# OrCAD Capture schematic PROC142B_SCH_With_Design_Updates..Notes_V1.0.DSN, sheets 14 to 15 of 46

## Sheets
14 12. PERIPHERAL POWER SUPPLY-2: size C; title: PERIPHERAL POWER SUPPLIES-2
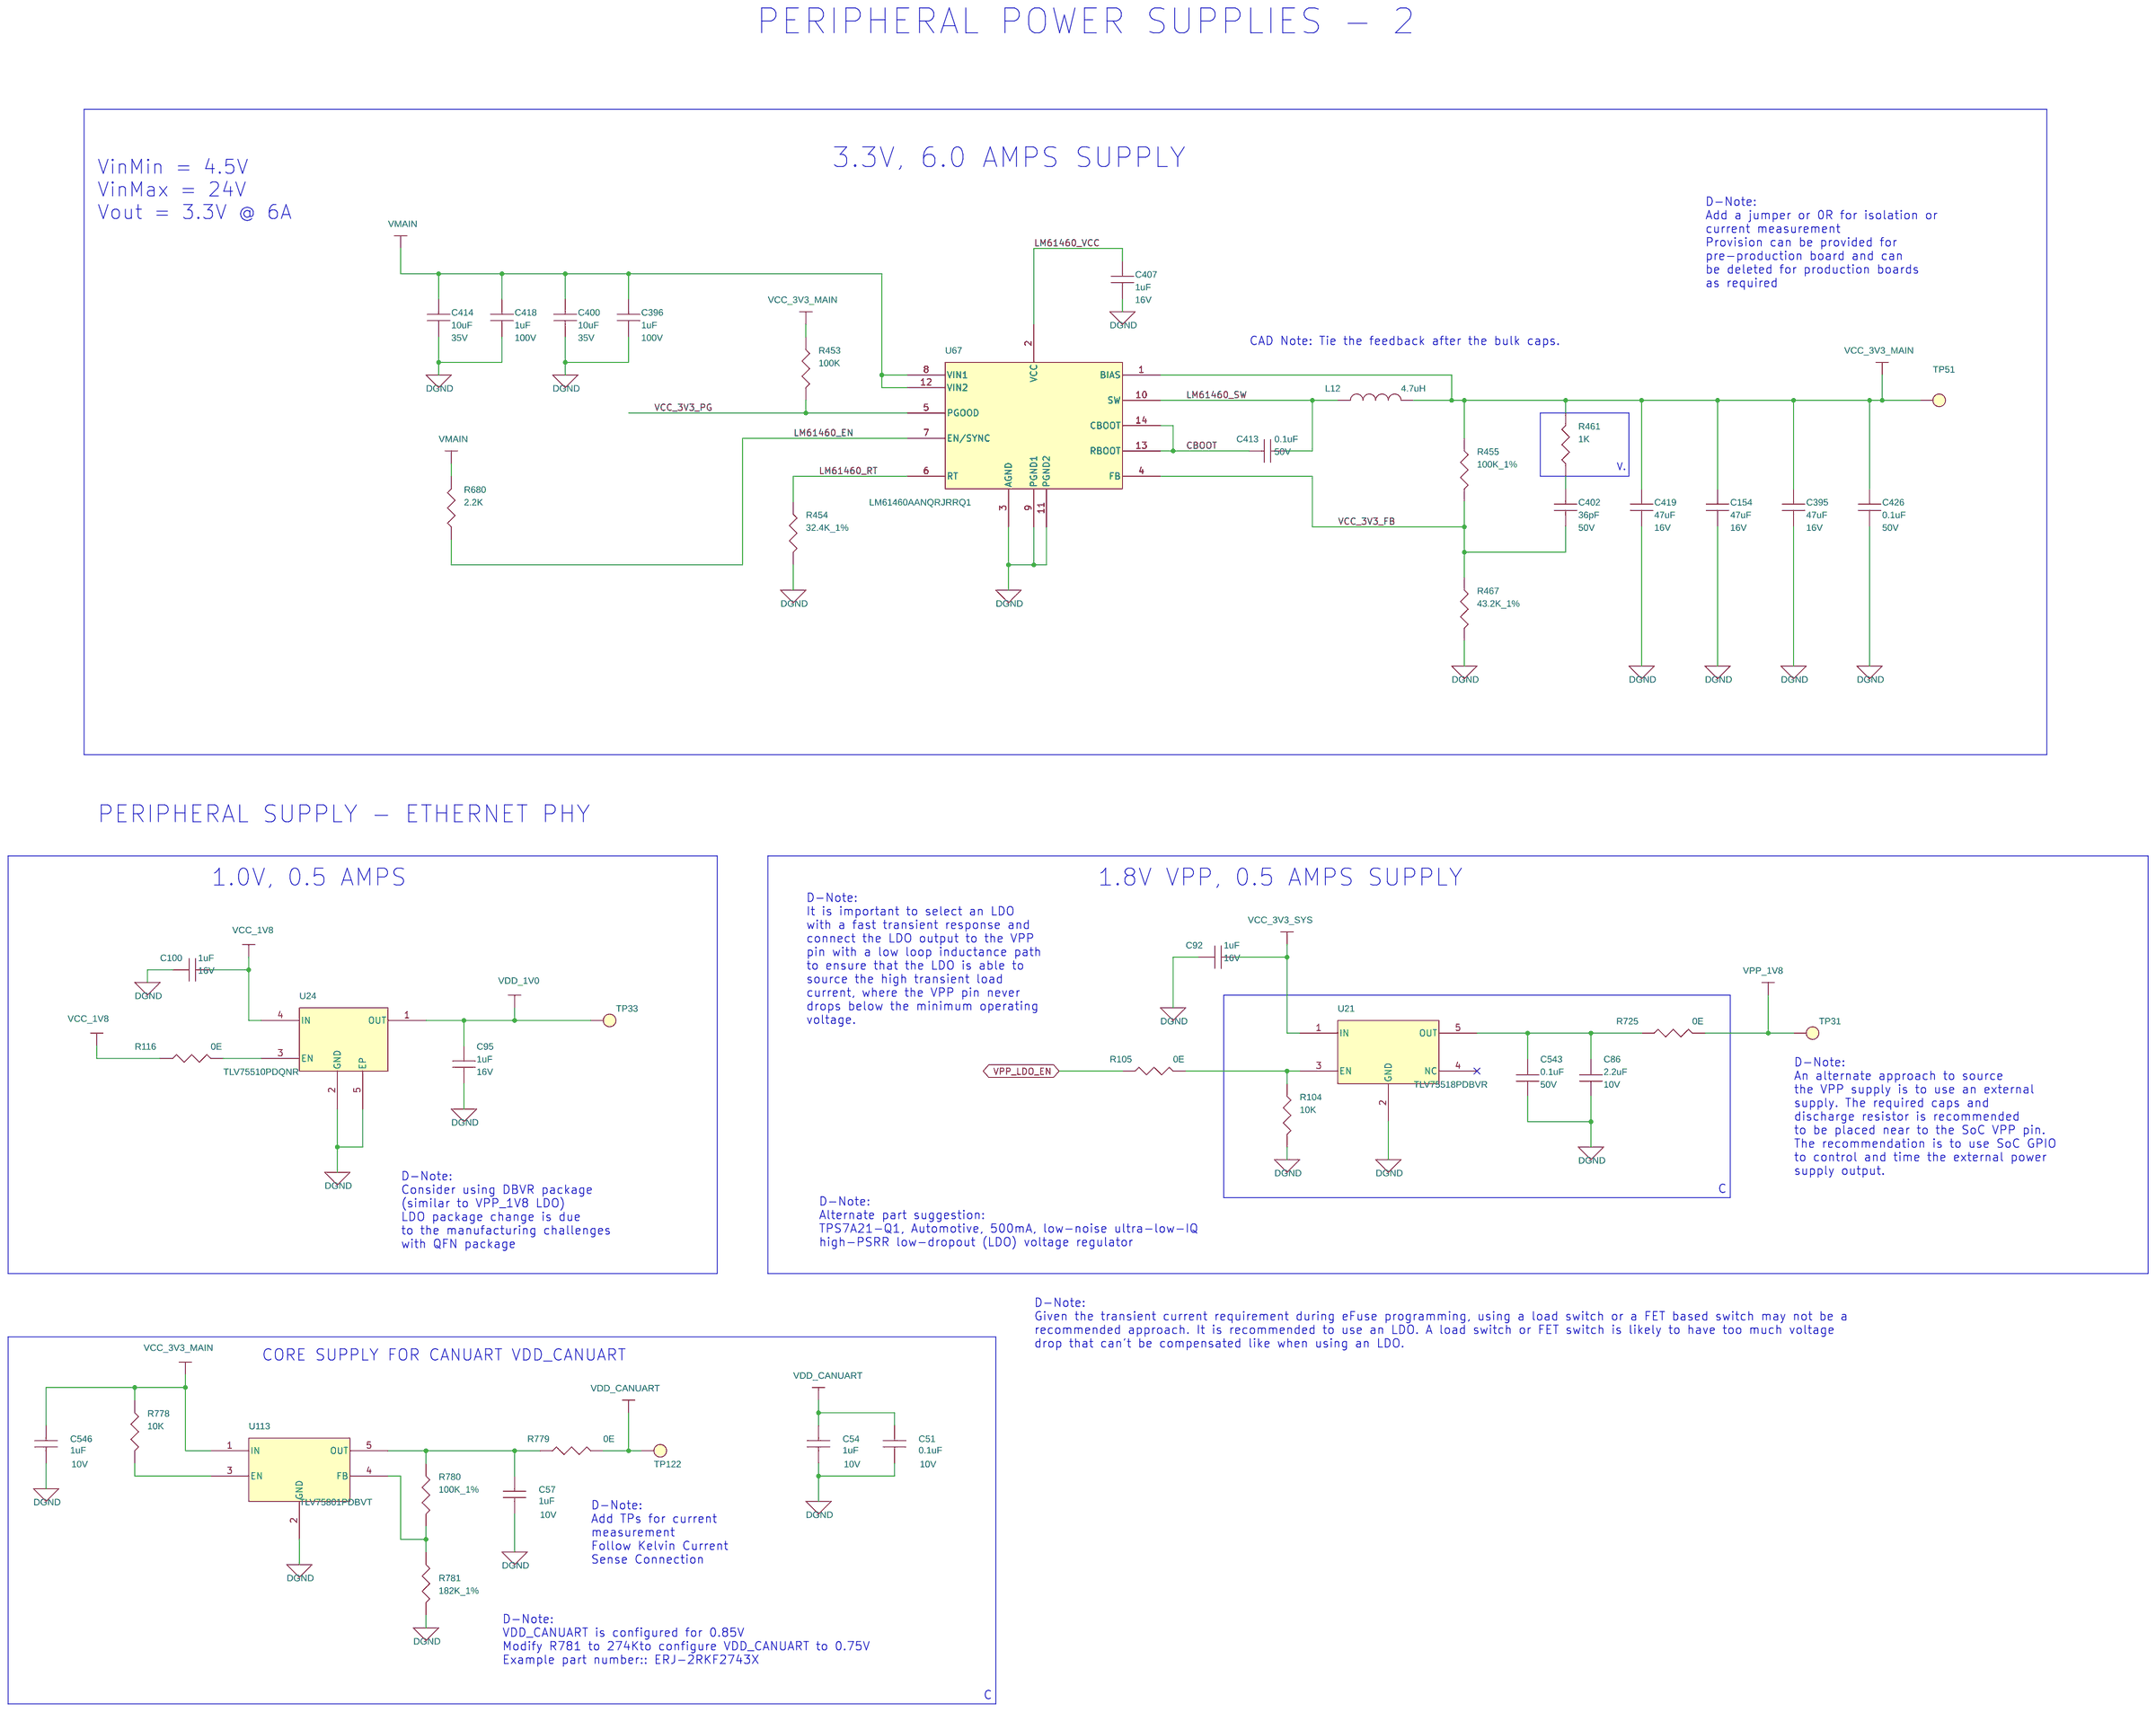
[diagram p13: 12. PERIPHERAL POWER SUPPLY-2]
15 13. FULTON PMIC: size C; title: SOC POWER SUPPLIES-PMIC BASED WITH SOC CURRENT MEASUREMENT SHUNTS
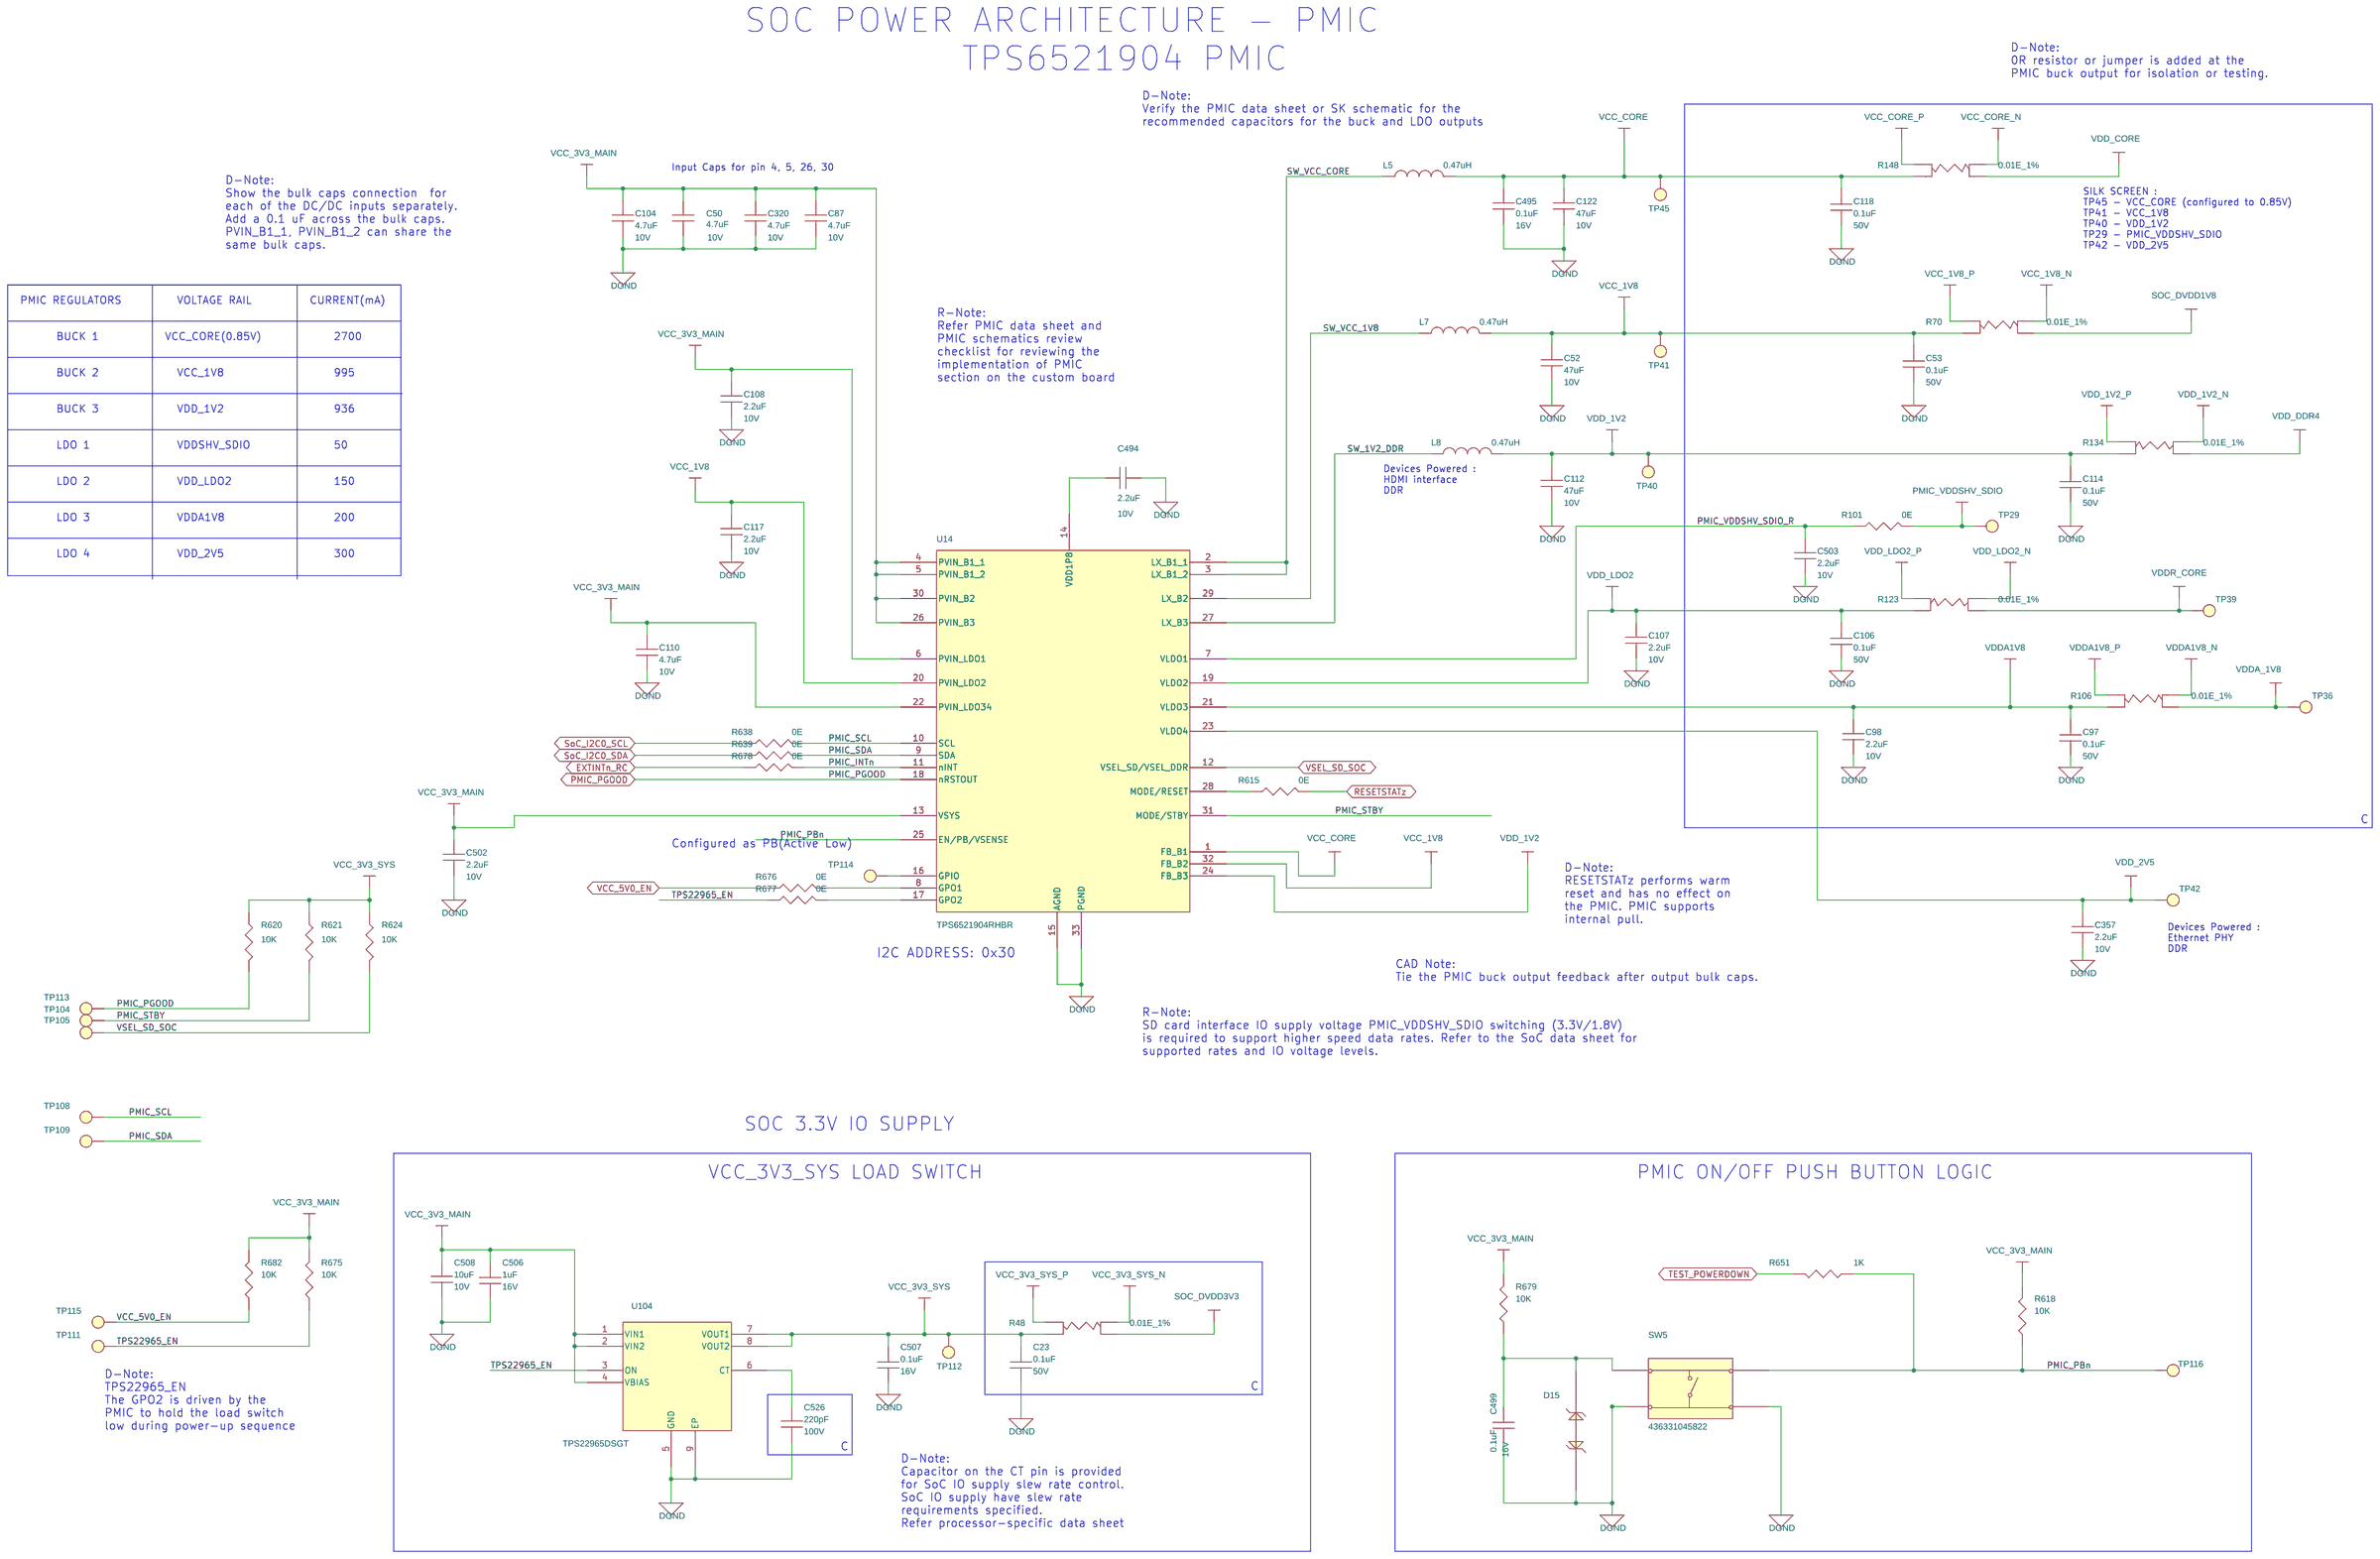
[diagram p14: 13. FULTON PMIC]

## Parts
sheet 12. PERIPHERAL POWER SUPPLY-2
C51  0.1uF  [CAP0201_0-5]
C54  1uF  [CAP0201_0-5]
C57  1uF  [CAP0201_0-5]
C86  2.2uF  [CAP0201_0-5]
C92  1uF  [CAP0201_0-5]
C95  1uF  [CAP0201_0-5]
C100  1uF  [CAP0201_0-5]
C154  47uF  [CAP1210_2-75]
C395  47uF  [CAP1210_2-75]
C396  1uF  [CAP0805_1-5]
C400  10uF  [CAP0603_1]
C402  36pF  [CAP0402_0-75]
C407  1uF  [CAP0201_0-5]
C413  0.1uF  [CAP0402_0-75]
C414  10uF  [CAP0603_1]
C418  1uF  [CAP0805_1-5]
C419  47uF  [CAP1210_2-75]
C426  0.1uF  [CAP0402_0-75]
C543  0.1uF  [CAP0402_0-75]
C546  1uF  [CAP0201_0-5]
L12  4.7uH  [IND_XAL6060_260X270_SMD_6-1]
R104  10K  [RES0201_0-5]
R105  0E  [RES0201_0-5]
R116  0E  [RES0201_0-5]
R453  100K  [RES0402_0-5]
R454  32.4K_1%  [RES0402_0-5]
R455  100K_1%  [RES0402_0-5]
R461  1K  [RES0402_0-5]
R467  43.2K_1%  [RES0402_0-5]
R680  2.2K  [RES0402_0-5]
R725  0E  [RES0805_0-75]
R778  10K  [RES0201_0-5]
R779  0E  [RES0402_0-5]
R780  100K_1%  [RES0402_0-5]
R781  182K_1%  [RES0402_0-5]
TP31  TP20_SMD  [TP20_SMD]
TP33  TP20_SMD  [TP20_SMD]
TP51  TP20_SMD  [TP20_SMD]
TP122  TP20_SMD  [TP20_SMD]
U21  TLV75518PDBVR  [SOT23-5_1-5]
U24  TLV75510PDQNR  [X2SON4_TLV71318P_40X40_0-4]
U67  LM61460AANQRJRRQ1  [VQFNHR14_LM61460_160X140_1]
U113  TLV75801PDBVT  [SOT23-5_1-5]
sheet 13. FULTON PMIC
C23  0.1uF  [CAP0402_0-75]
C50  4.7uF  [CAP0402_0-75]
C52  47uF  [CAP0805_1-5]
C53  0.1uF  [CAP0402_0-75]
C87  4.7uF  [CAP0402_0-75]
C97  0.1uF  [CAP0402_0-75]
C98  2.2uF  [CAP0201_0-5]
C104  4.7uF  [CAP0402_0-75]
C106  0.1uF  [CAP0402_0-75]
C107  2.2uF  [CAP0201_0-5]
C108  2.2uF  [CAP0201_0-5]
C110  4.7uF  [CAP0402_0-75]
C112  47uF  [CAP0805_1-5]
C114  0.1uF  [CAP0402_0-75]
C117  2.2uF  [CAP0201_0-5]
C118  0.1uF  [CAP0402_0-75]
C122  47uF  [CAP0805_1-5]
C320  4.7uF  [CAP0402_0-75]
C357  2.2uF  [CAP0201_0-5]
C494  2.2uF  [CAP0201_0-5]
C495  0.1uF  [CAP0201_0-5]
C499  0.1uF  [CAP0201_0-5]
C502  2.2uF  [CAP0201_0-5]
C503  2.2uF  [CAP0201_0-5]
C506  1uF  [CAP0201_0-5]
C507  0.1uF  [CAP0201_0-5]
C508  10uF  [CAP0402_0-75]
C526  220pF  [CAP0402_0-75]
D15  TPD1E10B06DPYR  [DIO_DFN0402_0-5]
L5  0.47uH  [IND0806_1-2]
L7  0.47uH  [IND0806_1-2]
L8  0.47uH  [IND0806_1-2]
R48  0.01E_1%  [RES_KRL3216T4_1206-4_0-7]
R70  0.01E_1%  [RES_KRL3216T4_1206-4_0-7]
R101  0E  [RES0402_0-5]
R106  0.01E_1%  [RES_KRL3216T4_1206-4_0-7]
R123  0.01E_1%  [RES_KRL3216T4_1206-4_0-7]
R134  0.01E_1%  [RES_KRL3216T4_1206-4_0-7]
R148  0.01E_1%  [RES_KRL3216T4_1206-4_0-7]
R615  0E  [RES0402_0-5]
R618  10K  [RES0201_0-5]
R620  10K  [RES0201_0-5]
R621  10K  [RES0201_0-5]
R624  10K  [RES0201_0-5]
R638  0E  [RES0201_0-5]
R639  0E  [RES0201_0-5]
R651  1K  [RES0402_0-5]
R675  10K  [RES0201_0-5]
R676  0E  [RES0201_0-5]
R677  0E  [RES0201_0-5]
R678  0E  [RES0201_0-5]
R679  10K  [RES0201_0-5]
R682  10K  [RES0201_0-5]
SW5  436331045822  [SW4_436331045822_190X190_SMD_1-7]
TP29  TP20_SMD  [TP20_SMD]
TP36  TP20_SMD  [TP20_SMD]
TP39  TP20_SMD  [TP20_SMD]
TP40  TP20_SMD  [TP20_SMD]
TP41  TP20_SMD  [TP20_SMD]
TP42  TP20_SMD  [TP20_SMD]
TP45  TP20_SMD  [TP20_SMD]
TP104  TP20_SMD  [TP20_SMD]
TP105  TP20_SMD  [TP20_SMD]
TP108  TP20_SMD  [TP20_SMD]
TP109  TP20_SMD  [TP20_SMD]
TP111  TP20_SMD  [TP20_SMD]
TP112  TP20_SMD  [TP20_SMD]
TP113  TP20_SMD  [TP20_SMD]
TP114  TP20_SMD  [TP20_SMD]
TP115  TP20_SMD  [TP20_SMD]
TP116  TP20_SMD  [TP20_SMD]
U14  TPS6521904RHBR  [QFN32_19-68_200X200_1_EP3-8]
U104  TPS22965DSGT  [WSON8_19-68_80X80_0-8]

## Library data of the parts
C51 = CAP: CAP CERAMIC 0.1uF 10V 10% X5R 0201; Chkd/date: MANIRAJA/290421; Crtd /date: ALVY/290421; Custom_Duty: 15%; Customs_HS_Code: 85322990; Distributor_name: DIGIKEY; Distributor_part_number: 1276-1115-1-ND; Footprint Path: Y:\MIS_DATABASE\Library\ALTIUM_TOOL\PCB_FOOTPRINTS\Altium_Footprint_Lib.PcbLib; Height: 0.33MM; Library Path: Y:\MIS_DATABASE\Library\ALTIUM_TOOL\SCHEMATICS_PARTS\MS_DISCRETE_Library.schlib; Mfr_name: SAMSUNG; Mfr_part_number: CL03A104KP3NNNC; Mistral Part No: 120009050017-R; Package: 0201; Part_type: CAPACITORS\CERAMIC; Project: SRMS-SAR_BRD; RoHS: RoHS; Temperature: -55°C+85°C; Tolerance: 10%; Voltage: 10V; Wattage: NA; Weight: 0.33mg; Datasheet: Y:\MIS_DATABASE\DATASHEETS\CAPACITORS\CL03A104KP3NNNC.PDF
C54 C57 C546 = CAP: CAP CERAMIC 1uF 10V 20% X5R 0201; Chkd/date: NAVEED/070415; Crtd /date: VASANTHA/230314; Custom_Duty: 15%; Customs_HS_Code: 85322990; Distributor_name: DIGIKEY; Distributor_part_number: 1276-1324-1-ND; Footprint Path: Y:\MIS_DATABASE\Library\ALTIUM_TOOL\PCB_FOOTPRINTS\Altium_Footprint_Lib.PcbLib; Height: 0.35MM; Library Path: Y:\MIS_DATABASE\Library\ALTIUM_TOOL\SCHEMATICS_PARTS\MS_DISCRETE_Library.schlib; Mfr_name: SAMSUNG; Mfr_part_number: CL03A105MP3NSNC; Mistral Part No: 120015030003-R; Package: 0201; Part_type: CAPACITORS\CERAMIC; Project: DUET BOARDS; RoHS: RoHS; Temperature: -55°C+85°C; Tolerance: 20%; Voltage: 10V; Wattage: NA; Weight: 0.17mg; Datasheet: Y:\MIS_DATABASE\DATASHEETS\CAPACITORS\CL03A105MP3NSNC.PDF
C86 C494 C502 = CAP: CAP CERAMIC 2.2uF 10V 10% X5R 0201; Chkd/date: MANIRAJA/220918; Crtd /date: MANIRAJA/220918; Custom_Duty: 15%; Customs_HS_Code: 85322990; Distributor_name: DIGIKEY; Distributor_part_number: 490-13227-1-ND; Footprint Path: Y:\MIS_DATABASE\Library\ALTIUM_TOOL\PCB_FOOTPRINTS\Altium_Footprint_Lib.PcbLib; Height: 0.39MM; Library Path: Y:\MIS_DATABASE\Library\ALTIUM_TOOL\SCHEMATICS_PARTS\MS_DISCRETE_Library.schlib; Mfr_name: MURATA; Mfr_part_number: GRM033R61A225KE47D; Mistral Part No: 120018090044-R; Package: 0201; Part_type: CAPACITORS\CERAMIC; Project: TI_60GHz-AOP; RoHS: RoHS; Temperature: -55°C+85°C; Tolerance: 10%; Voltage: 10V; Wattage: NA; Weight: 0.33mg; Datasheet: Y:\MIS_DATABASE\DATASHEETS\CAPACITORS\GRM033R61A225KE47D.PDF
C92 C95 C100 C407 C506 = CAP: CAP CERAMIC 1uF 16V 20% X5R 0201; Chkd/date: MANIRAJA/300520; Crtd /date: ALVY/260520; Custom_Duty: 15%; Customs_HS_Code: 85322990; Distributor_name: DIGIKEY; Distributor_part_number: 490-18654-1-ND; Footprint Path: Y:\MIS_DATABASE\Library\ALTIUM_TOOL\PCB_FOOTPRINTS\Altium_Footprint_Lib.PcbLib; Height: 0.39MM; Library Path: Y:\MIS_DATABASE\Library\ALTIUM_TOOL\SCHEMATICS_PARTS\MS_DISCRETE_Library.schlib; Mfr_name: MURATA; Mfr_part_number: GRM033R61C105ME15D; Mistral Part No: 120018090038-R; Package: 0201; Part_type: CAPACITORS\CERAMIC; Project: QCS610_NANOSOM; RoHS: RoHS; Temperature: -55°C+85°C; Tolerance: 20%; Voltage: 16V; Wattage: NA; Weight: 0.33mg; Datasheet: Y:\MIS_DATABASE\DATASHEETS\CAPACITORS\GRM033R61C105ME15.PDF
C154 C395 C419 = CAP: CAP CERAMIC 47uF 16V 10% X6S 1210; Chkd/date: ALVY/010721; Crtd /date: MANIRAJA/010721; Custom_Duty: 15%; Customs_HS_Code: 85322990; Distributor_name: DIGIKEY; Distributor_part_number: 490-10531-1-ND; Footprint Path: Y:\MIS_DATABASE\Library\ALTIUM_TOOL\PCB_FOOTPRINTS\Altium_Footprint_Lib.PcbLib; Height: 2.70MM; Library Path: Y:\MIS_DATABASE\Library\ALTIUM_TOOL\SCHEMATICS_PARTS\MS_DISCRETE_Library.schlib; Mfr_name: MURATA; Mfr_part_number: GRM32EC81C476KE15L; Mistral Part No: 120021070001-R; Package: 1210; Part_type: CAPACITORS\CERAMIC; Project: TI_AM263X_CC; RoHS: RoHS; Temperature: -55°C+105°C; Tolerance: 10%; Voltage: 16V; Wattage: NA; Weight: 100mg; Datasheet: Y:\MIS_DATABASE\DATASHEETS\CAPACITORS\GRM32EC81C476KE15.PDF
C396 C418 = CAP: CAP CERAMIC 1uF 100V 10% X7S 0805; Chkd/date: MANIRAJA/160921; Crtd /date: ALVY/150921; Custom_Duty: 15%; Customs_HS_Code: 85322990; Distributor_name: DIGIKEY; Distributor_part_number: 490-14464-1-ND; Footprint Path: Y:\MIS_DATABASE\Library\ALTIUM_TOOL\PCB_FOOTPRINTS\Altium_Footprint_Lib.PcbLib; Height: 1.45MM; Library Path: Y:\MIS_DATABASE\Library\ALTIUM_TOOL\SCHEMATICS_PARTS\MS_DISCRETE_Library.schlib; Mfr_name: MURATA; Mfr_part_number: GRM21BC72A105KE01L; Mistral Part No: 120013030002-R; Package: 0805; Part_type: CAPACITORS\CERAMIC; Project: TI_AM62x SKEVM_BRD; RoHS: RoHS; Temperature: -55°C+125°C; Tolerance: 10%; Voltage: 100V; Wattage: NA; Weight: 6.4mg; Datasheet: Y:\MIS_DATABASE\DATASHEETS\CAPACITORS\GRM21BC72A105KE01.PDF
C400 C414 = CAP: CAP CERAMIC 10uF 35V 20% X5R 0603; Chkd/date: MANIRAJA/170519; Crtd /date: ALVY/160519; Custom_Duty: 15%; Customs_HS_Code: 85322990; Distributor_name: DIGIKEY; Distributor_part_number: 490-13248-1-ND; Footprint Path: Y:\MIS_DATABASE\Library\ALTIUM_TOOL\PCB_FOOTPRINTS\Altium_Footprint_Lib.PcbLib; Height: 1.00MM; Library Path: Y:\MIS_DATABASE\Library\ALTIUM_TOOL\SCHEMATICS_PARTS\MS_DISCRETE_Library.schlib; Mfr_name: MURATA; Mfr_part_number: GRM188R6YA106MA73D; Mistral Part No: 120019050016-R; Package: 0603; Part_type: CAPACITORS\CERAMIC; Project: BRUKER_SD820_COMMONDO; RoHS: RoHS; Temperature: -55°C+85°C; Tolerance: 20%; Voltage: 35V; Wattage: NA; Weight: 9mg; Datasheet: Y:\MIS_DATABASE\DATASHEETS\CAPACITORS\GRM188R6YA106MA73.PDF
C402 = CAP: CAP CERAMIC 36pF 50V 2% HI-Q C0G(NP0) 0402; Chkd/date: MANIRAJA/061021; Crtd /date: ALVY/051021; Custom_Duty: 15%; Customs_HS_Code: 85322990; Distributor_name: DIGIKEY; Distributor_part_number: 490-GJM1555C1H360GB01DTR-ND; Footprint Path: Y:\MIS_DATABASE\Library\ALTIUM_TOOL\PCB_FOOTPRINTS\Altium_Footprint_Lib.PcbLib; Height: 0.55MM; Library Path: Y:\MIS_DATABASE\Library\ALTIUM_TOOL\SCHEMATICS_PARTS\MS_DISCRETE_Library.schlib; Mfr_name: MURATA; Mfr_part_number: GJM1555C1H360GB01D; Mistral Part No: 120021100002-R; Package: 0402; Part_type: CAPACITORS\CERAMIC; Project: TI_AM62x SKEVM_BRD; RoHS: RoHS; Temperature: -55°C+125°C; Tolerance: 2%; Voltage: 50V; Wattage: NA; Weight: 1.5mg; Datasheet: Y:\MIS_DATABASE\DATASHEETS\CAPACITORS\GJM1555C1H360GB01.PDF
C413 C426 = CAP: CAP CERAMIC 0.1uF 50V 10% X7R 0402; Chkd/date: MANIRAJA/261020; Crtd /date: ALVY/211020; Custom_Duty: 15%; Customs_HS_Code: 85322990; Distributor_name: DIGIKEY; Distributor_part_number: 490-10700-1-ND; Footprint Path: Y:\MIS_DATABASE\Library\ALTIUM_TOOL\PCB_FOOTPRINTS\Altium_Footprint_Lib.PcbLib; Height: 0.55MM; Library Path: Y:\MIS_DATABASE\Library\ALTIUM_TOOL\SCHEMATICS_PARTS\MS_DISCRETE_Library.schlib; Mfr_name: MURATA; Mfr_part_number: GRM155R71H104KE14D; Mistral Part No: 120011100014-R; Package: 0402; Part_type: CAPACITORS\CERAMIC; Project: J7_CP; RoHS: RoHS; Temperature: -55°C+125°C; Tolerance: 10%; Voltage: 50V; Wattage: NA; Weight: 3.1mg; Datasheet: Y:\MIS_DATABASE\DATASHEETS\CAPACITORS\GRM155R71H104KE14.PDF
C23 C53 C97 C106 C114 C118 C543 = CAP: CAP CERAMIC 0.1uF 50V 10% X7R 0402; Alt_Mfr_name: YAGEO AMERICA; Alt_Mfr_part_number: CC0402KRX5R8BB104; Chkd/date: MANIRAJA/261020; Crtd /date: ALVY/211020; Custom_Duty: 15%; Customs_HS_Code: 85322990; Distributor_name: DIGIKEY; Distributor_part_number: 490-10700-1-ND; Footprint Path: Y:\MIS_DATABASE\Library\ALTIUM_TOOL\PCB_FOOTPRINTS\Altium_Footprint_Lib.PcbLib; Height: 0.55MM; Library Path: Y:\MIS_DATABASE\Library\ALTIUM_TOOL\SCHEMATICS_PARTS\MS_DISCRETE_Library.schlib; Mfr_name: MURATA; Mfr_part_number: GRM155R71H104KE14D; Mistral Part No: 120011100014-R; Package: 0402; Part_type: CAPACITORS\CERAMIC; Project: J7_CP; RoHS: RoHS; Temperature: -55°C+125°C; Tolerance: 10%; Voltage: 50V; Wattage: NA; Weight: 3.1mg; Datasheet: Y:\MIS_DATABASE\DATASHEETS\CAPACITORS\GRM155R71H104KE14.PDF
L12 = INDUCTOR: IND POWER 4.7uH 11A 20% SMD; Chkd/date: VASANTHA/090317; Crtd /date: MANIRAJA/090317; Custom_Duty: 15%; Customs_HS_Code: 85412900; Distributor_name: MOUSER; Distributor_part_number: 994-XAL6060-472MEB; Footprint Path: Y:\MIS_DATABASE\Library\ALTIUM_TOOL\PCB_FOOTPRINTS\Altium_Footprint_Lib.PcbLib; Height: 6.10MM; Library Path: Y:\MIS_DATABASE\Library\ALTIUM_TOOL\SCHEMATICS_PARTS\MS_DISCRETE_Library.schlib; Mfr_name: COILCRAFT; Mfr_part_number: XAL6060-472MEB; Mistral Part No: 130015090013-R; Package: SMD; Project: OCTBTS_3000; RoHS: RoHS; Temperature: -40°C+125°C; Tolerance: 20%; Voltage: NA; Wattage: NA; Weight: 1600g; Datasheet: Y:\MIS_DATABASE\DATASHEETS\DISCRETES\INDUCTORS\XAL6060-SER.PDF
R104 R778 = RESISTOR: RES 10K 1/20W 5% 0201; Chkd/date: MANIRAJA/050517; Crtd /date: MANIRAJA/050517; Custom_Duty: 15%; Customs_HS_Code: 85332119; Distributor_name: DIGIKEY; Distributor_part_number: 311-10KNCT-ND; Footprint Path: Y:\MIS_DATABASE\Library\ALTIUM_TOOL\PCB_FOOTPRINTS\Altium_Footprint_Lib.PcbLib; Height: 0.26MM; Library Path: Y:\MIS_DATABASE\Library\ALTIUM_TOOL\SCHEMATICS_PARTS\MS_DISCRETE_Library.schlib; Mfr_name: YAGEO AMERICA; Mfr_part_number: RC0201JR-0710KL; Mistral Part No: 110010070051-R; Package: 0201; Part_type: RESISTORS\FIXED; Project: GOLDEN-I LITE; RoHS: RoHS; Temperature: -55°C+125°C; Tolerance: 5%; Voltage: NA; Wattage: 1/20W; Weight: 0.17mg; Datasheet: Y:\MIS_DATABASE\DATASHEETS\RESISTORS\RCXXXXL-SER_MAR18.PDF
R105 R116 R638 R639 R676-R678 = RESISTOR: RES 0E 1/20W 5% 0201; Chkd/date: NAVEED/301214; Crtd /date: MUDDU/120710; Custom_Duty: 15%; Customs_HS_Code: 85332119; Distributor_name: DIGIKEY; Distributor_part_number: 311-0.0NCT-ND; Footprint Path: Y:\MIS_DATABASE\Library\ALTIUM_TOOL\PCB_FOOTPRINTS\Altium_Footprint_Lib.PcbLib; Height: 0.26MM; Library Path: Y:\MIS_DATABASE\Library\ALTIUM_TOOL\SCHEMATICS_PARTS\MS_DISCRETE_Library.schlib; Mfr_name: YAGEO AMERICA; Mfr_part_number: RC0201JR-070RL; Mistral Part No: 110010070067-R; Package: 0201; Part_type: RESISTORS\FIXED; Project: PB_BUGBASE; RoHS: RoHS; Temperature: -55°C+125°C; Tolerance: 5%; Voltage: NA; Wattage: 1/20W; Weight: 0.17mg; Datasheet: Y:\MIS_DATABASE\DATASHEETS\RESISTORS\RCXXXXL-SER_MAR18.PDF
R453 = RESISTOR: RES 100K 1/16W 5% 0402; Chkd/date: MANIRAJA/100717; Crtd /date: MANIRAJA/100717; Custom_Duty: 15%; Customs_HS_Code: 85332119; Distributor_name: DIGIKEY; Distributor_part_number: 311-100KJRCT-ND; Footprint Path: Y:\MIS_DATABASE\Library\ALTIUM_TOOL\PCB_FOOTPRINTS\Altium_Footprint_Lib.PcbLib; Height: 0.40MM; Library Path: Y:\MIS_DATABASE\Library\ALTIUM_TOOL\SCHEMATICS_PARTS\MS_DISCRETE_Library.schlib; Mfr_name: YAGEO AMERICA; Mfr_part_number: RC0402JR-07100KL; Mistral Part No: 110011060002-R; Package: 0402; Part_type: RESISTORS\FIXED; Project: DM8147_PCI CARD; RoHS: RoHS; Temperature: -55°C+155°C; Tolerance: 5%; Voltage: NA; Wattage: 1/16W; Weight: 0.65mg; Datasheet: Y:\MIS_DATABASE\DATASHEETS\RESISTORS\RCXXXXL-SER_MAR18.PDF
R454 = RESISTOR: RES 32.4K 1/16W 1% 0402; Chkd/date: MANIRAJA/080420; Crtd /date: ALVY/080420; Custom_Duty: 15%; Customs_HS_Code: 85332119; Distributor_name: DIGIKEY; Distributor_part_number: 541-32.4KLCT-ND; Footprint Path: Y:\MIS_DATABASE\Library\ALTIUM_TOOL\PCB_FOOTPRINTS\Altium_Footprint_Lib.PcbLib; Height: 0.40MM; Library Path: Y:\MIS_DATABASE\Library\ALTIUM_TOOL\SCHEMATICS_PARTS\MS_DISCRETE_Library.schlib; Mfr_name: VISHAY; Mfr_part_number: CRCW040232K4FKED; Mistral Part No: 110020040003-R; Package: 0402; Part_type: RESISTORS\FIXED; Project: HSDTRS_FEE_BRD; RoHS: RoHS; Temperature: -55°C+155°C; Tolerance: 1%; Voltage: NA; Wattage: 1/16W; Weight: 0.65mg; Datasheet: Y:\MIS_DATABASE\DATASHEETS\RESISTORS\CRCW0603.PDF
R455 R780 = RESISTOR: RES 100K 1/10W 1% 0402; Chkd/date: VASANTHA/201216; Crtd /date: MAZHAR/130306; Custom_Duty: 15%; Customs_HS_Code: 85332119; Distributor_name: DIGIKEY; Distributor_part_number: P100KLCT-ND; Footprint Path: Y:\MIS_DATABASE\Library\ALTIUM_TOOL\PCB_FOOTPRINTS\Altium_Footprint_Lib.PcbLib; Height: 0.40MM; Library Path: Y:\MIS_DATABASE\Library\ALTIUM_TOOL\SCHEMATICS_PARTS\MS_DISCRETE_Library.schlib; Mfr_name: PANASONIC-ECG; Mfr_part_number: ERJ-2RKF1003X; Mistral Part No: 110009030187-R; Package: 0402; Part_type: RESISTORS\FIXED; Project: J32; RoHS: RoHS; Temperature: -55°C+155°C; Tolerance: 1%; Voltage: NA; Wattage: 1/10W; Weight: 0.8mg; Datasheet: Y:\MIS_DATABASE\DATASHEETS\RESISTORS\PAN-ERJSER_NOV17.PDF
R461 R651 = RESISTOR: RES 1K 1/10W 5% 0402; Chkd/date: VASANTHA/201216; Crtd /date: MAZHAR/230805; Custom_Duty: 15%; Customs_HS_Code: 85332119; Distributor_name: DIGIKEY; Distributor_part_number: P1.0KJCT-ND; Footprint Path: Y:\MIS_DATABASE\Library\ALTIUM_TOOL\PCB_FOOTPRINTS\Altium_Footprint_Lib.PcbLib; Height: 0.40MM; Library Path: Y:\MIS_DATABASE\Library\ALTIUM_TOOL\SCHEMATICS_PARTS\MS_DISCRETE_Library.schlib; Mfr_name: PANASONIC-ECG; Mfr_part_number: ERJ-2GEJ102X; Mistral Part No: 110009030400-R; Package: 0402; Part_type: RESISTORS\FIXED; Project: HSE; RoHS: RoHS; Temperature: -55°C+155°C; Tolerance: 5%; Voltage: NA; Wattage: 1/10W; Weight: 0.8mg; Datasheet: Y:\MIS_DATABASE\DATASHEETS\RESISTORS\PAN-ERJSER_NOV17.PDF
R467 = RESISTOR: RES 43.2K 1/16W 1% 0402; Chkd/date: MANIRAJA/250821; Crtd /date: ALVY/250821; Custom_Duty: 15%; Customs_HS_Code: 85332119; Distributor_name: DIGIKEY; Distributor_part_number: 541-43.2KLCT-ND; Footprint Path: Y:\MIS_DATABASE\Library\ALTIUM_TOOL\PCB_FOOTPRINTS\Altium_Footprint_Lib.PcbLib; Height: 0.40MM; Library Path: Y:\MIS_DATABASE\Library\ALTIUM_TOOL\SCHEMATICS_PARTS\MS_DISCRETE_Library.schlib; Mfr_name: VISHAY; Mfr_part_number: CRCW040243K2FKED; Mistral Part No: 110021080019-R; Package: 0402; Part_type: RESISTORS\FIXED; Project: TI_AM62x SKEVM_BRD; RoHS: RoHS; Temperature: -55°C+155°C; Tolerance: 1%; Voltage: NA; Wattage: 1/16W; Weight: 0.65mg; Datasheet: Y:\MIS_DATABASE\DATASHEETS\RESISTORS\CRCW0603.PDF
R680 = RESISTOR: RES 2.2K 1/16W 5% 0402; Chkd/date: VASANTHA/061216; Crtd /date: BAVISH/021210; Custom_Duty: 15%; Customs_HS_Code: 85332119; Distributor_name: DIGIKEY; Distributor_part_number: 311-2.2KJRCT-ND; Footprint Path: Y:\MIS_DATABASE\Library\ALTIUM_TOOL\PCB_FOOTPRINTS\Altium_Footprint_Lib.PcbLib; Height: 0.40MM; Library Path: Y:\MIS_DATABASE\Library\ALTIUM_TOOL\SCHEMATICS_PARTS\MS_DISCRETE_Library.schlib; Mfr_name: YAGEO AMERICA; Mfr_part_number: RC0402JR-072K2L; Mistral Part No: 110010120018-R; Package: 0402; Part_type: RESISTORS\FIXED; Project: TE4; RoHS: RoHS; Temperature: -55°C+155°C; Tolerance: 5%; Voltage: NA; Wattage: 1/16W; Weight: 0.65mg; Datasheet: Y:\MIS_DATABASE\DATASHEETS\RESISTORS\RCXXXXL-SER_MAR18.PDF
R725 = RESISTOR: RES 0E 1/8W 5% 0805; Chkd/date: VASANTHA/130416; Crtd /date: JEBRAN/020316; Custom_Duty: 15%; Customs_HS_Code: 85332119; Distributor_name: DIGIKEY; Distributor_part_number: 311-0.0ARCT-ND; Footprint Path: Y:\MIS_DATABASE\Library\ALTIUM_TOOL\PCB_FOOTPRINTS\Altium_Footprint_Lib.PcbLib; Height: 0.60MM; Library Path: Y:\MIS_DATABASE\Library\ALTIUM_TOOL\SCHEMATICS_PARTS\MS_DISCRETE_Library.schlib; Mfr_name: YAGEO AMERICA; Mfr_part_number: RC0805JR-070RL; Mistral Part No: 110009030074-R; Package: 0805; Part_type: RESISTORS\FIXED; Project: ZK_BIOMETRIC; RoHS: RoHS; Temperature: -55°C+155°C; Tolerance: 5%; Voltage: NA; Wattage: 1/8W; Weight: 5.5mg; Datasheet: Y:\MIS_DATABASE\DATASHEETS\RESISTORS\RCXXXXL-SER_MAR18.PDF
R779 = RESISTOR: RES 0E 1/10W JUMPER 0402; Chkd/date: VASANTHA/061216; Crtd /date: NAVEED/201014; Custom_Duty: 15%; Customs_HS_Code: 85332119; Distributor_name: DIGIKEY; Distributor_part_number: P0.0JCT-ND; Footprint Path: Y:\MIS_DATABASE\Library\ALTIUM_TOOL\PCB_FOOTPRINTS\Altium_Footprint_Lib.PcbLib; Height: 0.40MM; IBISSP_MODLES: VALUE REPEATING 2 TIME; Library Path: Y:\MIS_DATABASE\Library\ALTIUM_TOOL\SCHEMATICS_PARTS\MS_DISCRETE_Library.schlib; Mfr_name: PANASONIC-ECG; Mfr_part_number: ERJ-2GE0R00X; Mistral Part No: 110018030052-R; Package: 0402; Part_type: RESISTORS\FIXED; Project: AEGIS POM; RoHS: RoHS; Temperature: -55°C+155°C; Tolerance: NA; Voltage: NA; Wattage: 1/10W; Weight: 0.8mg; Datasheet: Y:\MIS_DATABASE\DATASHEETS\RESISTORS\PAN-ERJSER_NOV17.PDF
R781 = RESISTOR: RES 182K 1/16W 1% 0402; Chkd/date: ALVY/210122; Crtd /date: TAMILARASU/210122; Custom_Duty: 15%; Customs_HS_Code: 85332119; Distributor_name: DIGIKEY; Distributor_part_number: YAG3015CT-ND; Footprint Path: Y:\MIS_DATABASE\Library\ALTIUM_TOOL\PCB_FOOTPRINTS\Altium_Footprint_Lib.PcbLib; Height: 0.40MM; Library Path: Y:\MIS_DATABASE\Library\ALTIUM_TOOL\SCHEMATICS_PARTS\MS_DISCRETE_Library.schlib; Mfr_name: YAGEO AMERICA; Mfr_part_number: RC0402FR-07182KL; Mistral Part No: 110022010016-R; Package: 0402; Part_type: RESISTORS\FIXED; Project: DLRL DIGITAL RECEIVER_BRD; RoHS: RoHS; Temperature: -55°C+155°C; Tolerance: 1%; Voltage: NA; Wattage: 1/16W; Weight: 0.65mg; Datasheet: Y:\MIS_DATABASE\DATASHEETS\RESISTORS\RCXXXXL-SER_MAR18.PDF
TP29 TP31 TP33 TP36 TP39-TP42 TP45 TP51 TP104 TP105 TP108 TP109 TP111-TP116 TP122 = TESTPOINT: TESTPOINT CIR 20 SMD; Chkd/date: SHREESHAIL/171006; Crtd /date: MAZHAR/171006; Custom_Duty: NA; Customs_HS_Code: NA; Distributor_name: NA; Distributor_part_number: NA; Footprint Path: Y:\MIS_DATABASE\Library\ALTIUM_TOOL\PCB_FOOTPRINTS\Altium_Footprint_Lib.PcbLib; Height: NA; Library Path: Y:\MIS_DATABASE\Library\ALTIUM_TOOL\SCHEMATICS_PARTS\MS_DISCRETE_Library.schlib; MECHANICAL 3D STEP FILE: NA; Mfr_name: LOCAL; Mistral Part No: NA; Package: SMD; Project: BT MODULE_CSRBC04; RoHS: NA; Temperature: NA; Tolerance: NA; Voltage: NA; Wattage: NA; Weight: NA; Datasheet: NA
U21 = TLV71318PDBVT_SOT23-5: IC 1.8V 500mA LOW IQ LDO REGULATOR SOT23-5; Chkd/date: MANIRAJA/120121; Crtd /date: MANIRAJA/120121; Custom_Duty: 15%; Customs_HS_Code: 85423100; Distributor_name: DIGIKEY; Distributor_part_number: 296-50410-1-ND; Footprint Path: Y:\MIS_DATABASE\Library\ALTIUM_TOOL\PCB_FOOTPRINTS\Altium_Footprint_Lib.PcbLib; Height: 1.45MM; Library Path: Y:\MIS_DATABASE\Library\ALTIUM_TOOL\SCHEMATICS_PARTS\MS_MISCPOWER_Library.schlib; Mfr_name: TEXAS INSTRUMENTS; Mistral Part No: 142021010009-R; Package: SOT23-5; Part_type: ICS\POWER\VOLTAGE REGULATOR; Project: TI_AM243x LP EVM; RoHS: RoHS; Temperature: -40°C+125°C; Tolerance: NA; Voltage: NA; Wattage: NA; Weight: 32.2mg; Datasheet: Y:\MIS_DATABASE\DATASHEETS\ICS\POWER\TLV755P.PDF
U24 = TLV71318PDQNR_X2SON4: IC 500mA 1V LOW IQ LDO REGULATOR X2SON-4; Chkd/date: MANIRAJA/240821; Crtd /date: ALVY/240821; Custom_Duty: 15%; Customs_HS_Code: 85423100; Distributor_name: DIGIKEY; Distributor_part_number: 296-51782-1-ND; Footprint Path: Y:\MIS_DATABASE\Library\ALTIUM_TOOL\PCB_FOOTPRINTS\Altium_Footprint_Lib.PcbLib; Height: 0.40MM; Library Path: Y:\MIS_DATABASE\Library\ALTIUM_TOOL\SCHEMATICS_PARTS\MS_MISCPOWER_Library.schlib; Mfr_name: TEXAS INSTRUMENTS; Mistral Part No: 142021080018-R; Package: X2SON-4; Part_type: ICS\POWER\VOLTAGE REGULATOR; Project: TI_AM62x SKEVM_BRD; RoHS: RoHS; Temperature: -40°C+125°C; Tolerance: NA; Voltage: NA; Wattage: NA; Weight: 1.1mg; Datasheet: Y:\MIS_DATABASE\DATASHEETS\ICS\POWER\TLV755P.PDF
U67 = LM61460_VQFNHR14: IC 6A ADJ AUTO LOW EMI SYNCHRONOUS STEP DOWN DC-DC CONVERTER VQFN-HR14; Chkd/date: ALVY/040221; Crtd /date: MANIRAJA/030221; Custom_Duty: 15%; Customs_HS_Code: 85423100; Distributor_name: DIGIKEY; Distributor_part_number: 296-LM61460AANQRJRRQ1TR-ND; Footprint Path: Y:\MIS_DATABASE\Library\ALTIUM_TOOL\PCB_FOOTPRINTS\Altium_Footprint_Lib.PcbLib; Height: 1.00MM; Library Path: Y:\MIS_DATABASE\Library\ALTIUM_TOOL\SCHEMATICS_PARTS\MS_MISCPOWER_Library.schlib; Mfr_name: TEXAS INSTRUMENTS; Mistral Part No: 142021020006-R; Package: VQFN-HR14; Part_type: ICS\POWER\DC-DC CONVERTER; Project: J7ES_SK_BRD; RoHS: RoHS; Temperature: -40°C+150°C; Tolerance: NA; Voltage: NA; Wattage: NA; Weight: NA; Datasheet: Y:\MIS_DATABASE\DATASHEETS\ICS\POWER\LM61460-Q1.PDF
U113 = TLV75801P_SOT23-5: IC 500mA ADJ LDO REGULATOR SOT23-5; Chkd/date: PRAVEEN/220922; Crtd /date: PRAVEEN/220922; Custom_Duty: 15%; Customs_HS_Code: 85423100; Distributor_name: DIGIKEY; Distributor_part_number: 296-TLV75801PDBVTCT-ND; Footprint Path: Y:\MIS_DATABASE\Library\ALTIUM_TOOL\PCB_FOOTPRINTS\Altium_Footprint_Lib.PcbLib; Height: 1.45MM; Library Path: Y:\MIS_DATABASE\Library\ALTIUM_TOOL\SCHEMATICS_PARTS\MS_MISCPOWER_Library.schlib; Mfr_name: TEXAS INSTRUMENTS; Mistral Part No: 142022090041-R; Package: SOT23-5; Part_type: ICS\POWER\VOLTAGE REGULATOR; Project: TRINETRA MISTRAL-DF; RoHS: RoHS; Temperature: -40°C+125°C; Tolerance: NA; Voltage: NA; Wattage: NA; Weight: NA; Datasheet: Y:\MIS_DATABASE\DATASHEETS\ICS\POWER\TLV75801PXXX.PDF
C50 C87 C104 C110 C320 = CAP: CAP CERAMIC 4.7uF 10V 20% X5R 0402; Chkd/date: MANIRAJA/110718; Crtd /date: ALVY/110718; Custom_Duty: 15%; Customs_HS_Code: 85322990; Distributor_name: DIGIKEY; Distributor_part_number: 490-14306-1-ND; Footprint Path: Y:\MIS_DATABASE\Library\ALTIUM_TOOL\PCB_FOOTPRINTS\Altium_Footprint_Lib.PcbLib; Height: 0.65MM; Library Path: Y:\MIS_DATABASE\Library\ALTIUM_TOOL\SCHEMATICS_PARTS\MS_DISCRETE_Library.schlib; Mfr_name: MURATA; Mfr_part_number: GRM155R61A475MEAAD; Mistral Part No: 120012060002-R; Package: 0402; Part_type: CAPACITORS\CERAMIC; Project: TI_J7SVB_PCIE_ADD-ON-CARD; RoHS: RoHS; Temperature: -55°C+85°C; Tolerance: 20%; Voltage: 10V; Wattage: NA; Weight: 14mg; Datasheet: Y:\MIS_DATABASE\DATASHEETS\CAPACITORS\GRM155R61A475MEAAD.PDF
C52 C112 C122 = CAP: CAP CERAMIC 47uF 10V 20% X5R 0805; Chkd/date: MANIRAJA/181018; Crtd /date: ALVY/181018; Custom_Duty: 15%; Customs_HS_Code: 85322990; Distributor_name: DIGIKEY; Distributor_part_number: 490-9961-1-ND; Footprint Path: Y:\MIS_DATABASE\Library\ALTIUM_TOOL\PCB_FOOTPRINTS\Altium_Footprint_Lib.PcbLib; Height: 1.45MM; Library Path: Y:\MIS_DATABASE\Library\ALTIUM_TOOL\SCHEMATICS_PARTS\MS_DISCRETE_Library.schlib; Manufacturer: MURATA; Mfr_name: MURATA; Mfr_part_number: GRM21BR61A476ME15L; Mistral Part No: 120014100011-R; Package: 0805; Part_type: CAPACITORS\CERAMIC; Project: RFID_MODULE-DESIGN; RoHS: RoHS; Temperature: -55°C+85°C; Tolerance: 20%; Voltage: 10V; Wattage: NA; Weight: 9.5mg; Datasheet: Y:\MIS_DATABASE\DATASHEETS\CAPACITORS\GRM21BR61A476ME15L.PDF
C98 C107 C108 C117 C357 C503 = CAP: CAP CERAMIC 2.2uF 10V 10% X5R 0201; Chkd/date: MANIRAJA/220918; Crtd /date: MANIRAJA/220918; Custom_Duty: 15%; Customs_HS_Code: 85322990; Distributor_name: DIGIKEY; Distributor_part_number: 490-13227-1-ND; Footprint Path: Y:\MIS_DATABASE\Library\ALTIUM_TOOL\PCB_FOOTPRINTS\Altium_Footprint_Lib.PcbLib; Height: 0.39MM; Library Path: Y:\MIS_DATABASE\Library\ALTIUM_TOOL\SCHEMATICS_PARTS\MS_DISCRETE_Library.schlib; Manufacturer: MURATA; Mfr_name: MURATA; Mfr_part_number: GRM033R61A225KE47D; Mistral Part No: 120018090044-R; Package: 0201; Part_type: CAPACITORS\CERAMIC; Project: TI_60GHz-AOP; RoHS: RoHS; Temperature: -55°C+85°C; Tolerance: 10%; Voltage: 10V; Wattage: NA; Weight: 0.33mg; Datasheet: Y:\MIS_DATABASE\DATASHEETS\CAPACITORS\GRM033R61A225KE47D.PDF
C495 = CAP: CAP CERAMIC 0.1uF 16V 10% X5R 0201; Chkd/date: MANIRAJA/230118; Crtd /date: MANIRAJA/230118; Custom_Duty: 15%; Customs_HS_Code: 85322990; Distributor_name: DIGIKEY; Distributor_part_number: 490-14305-1-ND; Footprint Path: Y:\MIS_DATABASE\Library\ALTIUM_TOOL\PCB_FOOTPRINTS\Altium_Footprint_Lib.PcbLib; Height: 0.33MM; Library Path: Y:\MIS_DATABASE\Library\ALTIUM_TOOL\SCHEMATICS_PARTS\MS_DISCRETE_Library.schlib; Mfr_name: MURATA; Mfr_part_number: GRM033R61C104KE14D; Mistral Part No: 120009030072-R; Package: 0201; Part_type: CAPACITORS\CERAMIC; Project: TI_MAXIE_CPB; RoHS: RoHS; Temperature: -55°C+85°C; Tolerance: 10%; Voltage: 16V; Wattage: NA; Weight: 0.33mg; Datasheet: Y:\MIS_DATABASE\DATASHEETS\CAPACITORS\GRM033R61C104KE14.PDF
C499 C507 = CAP: CAP CERAMIC 0.1uF 16V 10% X5R 0201; Alt_Mfr_name: YAGEO AMERICA; Alt_Mfr_part_number: CC0402KRX5R8BB104; Chkd/date: MANIRAJA/230118; Crtd /date: MANIRAJA/230118; Custom_Duty: 15%; Customs_HS_Code: 85322990; Distributor_name: DIGIKEY; Distributor_part_number: 490-14305-1-ND; Footprint Path: Y:\MIS_DATABASE\Library\ALTIUM_TOOL\PCB_FOOTPRINTS\Altium_Footprint_Lib.PcbLib; Height: 0.33MM; Library Path: Y:\MIS_DATABASE\Library\ALTIUM_TOOL\SCHEMATICS_PARTS\MS_DISCRETE_Library.schlib; Mfr_name: MURATA; Mfr_part_number: GRM033R61C104KE14D; Mistral Part No: 120009030072-R; Package: 0201; Part_type: CAPACITORS\CERAMIC; Project: TI_MAXIE_CPB; RoHS: RoHS; Temperature: -55°C+85°C; Tolerance: 10%; Voltage: 16V; Wattage: NA; Weight: 0.33mg; Datasheet: Y:\MIS_DATABASE\DATASHEETS\CAPACITORS\GRM033R61C104KE14.PDF
C508 = CAP: CAP CERAMIC 10uF 10V 20% X5R 0402; Chkd/date: MANIRAJA/300520; Crtd /date: ALVY/260520; Custom_Duty: 15%; Customs_HS_Code: 85322990; Distributor_name: DIGIKEY; Distributor_part_number: 490-GRM155R61A106ME11DTR-ND; Footprint Path: Y:\MIS_DATABASE\Library\ALTIUM_TOOL\PCB_FOOTPRINTS\Altium_Footprint_Lib.PcbLib; Height: 0.55MM; Library Path: Y:\MIS_DATABASE\Library\ALTIUM_TOOL\SCHEMATICS_PARTS\MS_DISCRETE_Library.schlib; Mfr_name: MURATA; Mfr_part_number: GRM155R61A106ME11D; Mistral Part No: 120013110019-R; Package: 0402; Part_type: CAPACITORS\CERAMIC; Project: QCS610_NANOSOM; RoHS: RoHS; Temperature: -55°C+85°C; Tolerance: 20%; Voltage: 10V; Wattage: NA; Weight: 3.1mg; Datasheet: Y:\MIS_DATABASE\DATASHEETS\CAPACITORS\MURATA-GXX-SER_NOV17.PDF
C526 = CAP: CAP CERAMIC 220pF 100V 5% C0G(NP0) 0402; Chkd/date: MANIRAJA/061021; Crtd /date: ALVY/051021; Custom_Duty: 15%; Customs_HS_Code: 85322990; Distributor_name: DIGIKEY; Distributor_part_number: 490-GRM1555C2A221JE01DTR-ND; Footprint Path: Y:\MIS_DATABASE\Library\ALTIUM_TOOL\PCB_FOOTPRINTS\Altium_Footprint_Lib.PcbLib; Height: 0.55MM; Library Path: Y:\MIS_DATABASE\Library\ALTIUM_TOOL\SCHEMATICS_PARTS\MS_DISCRETE_Library.schlib; Mfr_name: MURATA; Mfr_part_number: GRM1555C2A221JE01D; Mistral Part No: 120021100001-R; Package: 0402; Part_type: CAPACITORS\CERAMIC; Project: TI_AM62x SKEVM_BRD; RoHS: RoHS; Temperature: -55°C+125°C; Tolerance: 5%; Voltage: 100V; Wattage: NA; Weight: 1.6mg; Datasheet: Y:\MIS_DATABASE\DATASHEETS\CAPACITORS\GRM1555C2A221JE01.PDF
D15 = DIODE_SOD323: DIODE 1CH ESD PROTECTION X1SON2; Chkd/date: MANIRAJA/040420; Crtd /date: VASANTHA/181114; Custom_Duty: 15%; Customs_HS_Code: 85423100; Distributor_name: DIGIKEY; Distributor_part_number: 296-30406-1-ND; Footprint Path: Y:\MIS_DATABASE\Library\ALTIUM_TOOL\PCB_FOOTPRINTS\Altium_Footprint_Lib.PcbLib; Height: 0.45MM; Library Path: Y:\MIS_DATABASE\Library\ALTIUM_TOOL\SCHEMATICS_PARTS\MS_DISCRETE_Library.schlib; Mfr_name: TEXAS INSTRUMENTS; Mistral Part No: 130014110022-R; Package: X1SON2; Part_type: DIODE; Project: GALILEO_EVM; RoHS: RoHS; Temperature: -40°C+125°C; Tolerance: NA; Voltage: NA; Wattage: NA; Weight: 1mg; Datasheet: Y:\MIS_DATABASE\DATASHEETS\ICS\INTERFACE\TPD1E10B06-SER.PDF
L5 L7 L8 = INDUCTOR: IND CHIP 0.47uH 4.5A 20% 0806; Chkd/date: MANIRAJA/121020; Crtd /date: ALVY/121020; Custom_Duty: 24%; Customs_HS_Code: 85437099; Distributor_name: DIGIKEY; Distributor_part_number: DFE201612E-R47M=P2-ND; Footprint Path: Y:\MIS_DATABASE\Library\ALTIUM_TOOL\PCB_FOOTPRINTS\Altium_Footprint_Lib.PcbLib; Height: 1.20MM; Library Path: Y:\MIS_DATABASE\Library\ALTIUM_TOOL\SCHEMATICS_PARTS\MS_DISCRETE_Library.schlib; Mfr_name: MURATA; Mfr_part_number: DFE201612E-R47M=P2; Mistral Part No: 130020100030-R; Package: 0806; Project: AM64X_SKEVM; RoHS: RoHS; Temperature: -40°C+125°C; Tolerance: 20%; Voltage: NA; Wattage: NA; Weight: 18.8mg; Datasheet: Y:\MIS_DATABASE\DATASHEETS\DISCRETES\INDUCTORS\DFE201612E.PDF
R48 R70 R106 R123 R134 R148 = RESISTOR-4TERM: RES 0.01E 1W 1% 1206-4; Chkd/date: MANIRAJA/060318; Crtd /date: MANIRAJA/060318; Custom_Duty: 15%; Customs_HS_Code: 85332119; Distributor_name: DIGIKEY; Distributor_part_number: 408-1974-1-ND; Footprint Path: Y:\MIS_DATABASE\Library\ALTIUM_TOOL\PCB_FOOTPRINTS\Altium_Footprint_Lib.PcbLib; Height: 0.70MM; Library Path: Y:\MIS_DATABASE\Library\ALTIUM_TOOL\SCHEMATICS_PARTS\MS_DISCRETE_Library.schlib; Mfr_name: SUSUMU; Mfr_part_number: KRL3216T4A-M-R010-F-T1; Mistral Part No: 110018030003-R; Package: 1206-4; Part_type: RESISTORS\FIXED; Project: GRACO SMART MODULE; RoHS: RoHS; Temperature: -55°C+155°C; Tolerance: 1%; Voltage: NA; Wattage: 1W; Weight: 16.2mg; Datasheet: Y:\MIS_DATABASE\DATASHEETS\RESISTORS\KRL-SERIES.PDF
R101 R615 = RESISTOR: RES 0E 1/16W JUMPER 0402; Chkd/date: VASANTHA/201216; Crtd /date: MUDDU/190810; Custom_Duty: 15%; Customs_HS_Code: 85332119; Distributor_name: DIGIKEY; Distributor_part_number: 541-0.0JCT-ND; Footprint Path: Y:\MIS_DATABASE\Library\ALTIUM_TOOL\PCB_FOOTPRINTS\Altium_Footprint_Lib.PcbLib; Height: 0.40MM; Library Path: Y:\MIS_DATABASE\Library\ALTIUM_TOOL\SCHEMATICS_PARTS\MS_DISCRETE_Library.schlib; Mfr_name: VISHAY; Mfr_part_number: CRCW04020000Z0ED; Mistral Part No: 110010080019-R; Package: 0402; Part_type: RESISTORS\FIXED; Project: PB_BUGBASE; RoHS: RoHS; Temperature: -55°C+155°C; Tolerance: NA; Voltage: NA; Wattage: 1/16W; Weight: 0.65mg; Datasheet: Y:\MIS_DATABASE\DATASHEETS\RESISTORS\CRCW0603.PDF
R618 R620 R621 R624 R675 R679 R682 = RESISTOR: RES 10K 1/20W 5% 0201; Chkd/date: VASANTHA/061216; Crtd /date: MAZHAR/040505; Custom_Duty: 15%; Customs_HS_Code: 85332119; Distributor_name: DIGIKEY; Distributor_part_number: P10KAGCT-ND; Footprint Path: Y:\MIS_DATABASE\Library\ALTIUM_TOOL\PCB_FOOTPRINTS\Altium_Footprint_Lib.PcbLib; Height: 0.26MM; Library Path: Y:\MIS_DATABASE\Library\ALTIUM_TOOL\SCHEMATICS_PARTS\MS_DISCRETE_Library.schlib; Mfr_name: PANASONIC-ECG; Mfr_part_number: ERJ-1GEJ103C; Mistral Part No: 110010070051-R; Package: 0201; Part_type: RESISTORS\FIXED; Project: G4_SVGA; RoHS: RoHS; Temperature: -55°C+125°C; Tolerance: 5%; Voltage: NA; Wattage: 1/20W; Weight: 0.15mg; Datasheet: Y:\MIS_DATABASE\DATASHEETS\RESISTORS\PAN-ERJXGE-FEB06.PDF
SW5 = SW4_EVQP: SWITCH TACTILE SPST RT SMD; Chkd/date: MANIRAJA/051020; Crtd /date: ALVY/011020; Custom_Duty: 24%; Customs_HS_Code: 85369090; Distributor_name: DIGIKEY; Distributor_part_number: 732-7059-1-ND; Footprint Path: Y:\MIS_DATABASE\Library\ALTIUM_TOOL\PCB_FOOTPRINTS\Altium_Footprint_Lib.PcbLib; Height: 1.65MM; Library Path: Y:\MIS_DATABASE\Library\ALTIUM_TOOL\SCHEMATICS_PARTS\MS_SWITCH_Library.schlib; Mfr_name: WURTH ELECTRONICS; Mistral Part No: 130020100002-R; Package: SMD; Part_type: ELECTRO-MECHANICAL\SWITCH; Project: AM64X_SKEVM; RoHS: RoHS; Temperature: -40°C+85°C; Tolerance: NA; Voltage: NA; Wattage: NA; Weight: 50mg; Datasheet: Y:\MIS_DATABASE\DATASHEETS\MISC\SWITCHES\436331045822.PDF
U14 = TPS65219_QFN32: IC INTEGRATED POWER MANAGEMENT FOR ARM CORTEX-A53 PROCESSOR AND FPGA QFN32; Chkd/date: PRAVEEN/211022; Crtd /date: PRAVEEN/211022; Custom_Duty: 15%; Customs_HS_Code: 85423100; Distributor_name: NA; Distributor_part_number: NA; Footprint Path: Y:\MIS_DATABASE\Library\ALTIUM_TOOL\PCB_FOOTPRINTS\Altium_Footprint_Lib.PcbLib; Height: 1.00MM; Library Path: Y:\MIS_DATABASE\Library\ALTIUM_TOOL\SCHEMATICS_PARTS\MS_MISCPOWER_Library.schlib; Mfr_name: TEXAS INSTRUMENTS; Mistral Part No: 142022100015-R; Package: QFN32; Part_type: ICS\POWER\MANAGEMENT; Project: AM64X_SK; RoHS: NA; Temperature: -40°C+85°C; Tolerance: NA; Voltage: NA; Wattage: NA; Weight: NA; Datasheet: Y:\MIS_DATABASE\DATASHEETS\ICS\POWER\TPS6521904RHBR.PDF
U104 = TPS22965DSGT_WSON8: IC 5.7V 6A 1-CHANNEL 16mE ON-RESISTANCE LOAD SWITCH WSON8; Chkd/date: MANIRAJA/080817; Crtd /date: VASANTHA/280714; Custom_Duty: 15%; Customs_HS_Code: 85423100; Distributor_name: DIGIKEY; Distributor_part_number: 296-34943-1-ND; Footprint Path: Y:\MIS_DATABASE\Library\ALTIUM_TOOL\PCB_FOOTPRINTS\Altium_Footprint_Lib.PcbLib; Height: 0.80MM; Library Path: Y:\MIS_DATABASE\Library\ALTIUM_TOOL\SCHEMATICS_PARTS\MS_MISCPOWER_Library.schlib; Mfr_name: TEXAS INSTRUMENTS; Mistral Part No: 142014070020-R; Package: WSON8; Part_type: ICS\POWER\DRIVER; Project: DC_MIST_DIGITAL CARD; RoHS: RoHS; Temperature: -40°C+105°C; Tolerance: NA; Voltage: NA; Wattage: NA; Weight: 11mg; Datasheet: Y:\MIS_DATABASE\DATASHEETS\ICS\POWER\TPS22965-SER.PDF

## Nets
DGND: C23.1 C50.2 C51.2 C52.2 C53.1 C54.2 C57.2 C86.1 C87.2 C92.2 C95.2 C97.1 C98.2 C100.2 C104.2 C106.1 C107.2 C108.2 C110.2 C112.2 C114.1 C117.2 C118.1 C122.2 C154.2 C320.2 C357.2 C395.2 C396.2 C400.2 C407.2 C414.2 C418.2 C419.2 C426.2 C494.2 C495.2 C499.1 C502.2 C503.2 C506.1 C507.1 C508.2 C526.2 C543.1 C546.2 D15.1 R104.2 R454.2 R467.2 R781.2 SW5.2 SW5.4 U14.15(AGND) U14.33(PGND) U21.2(GND) U24.2(GND) U24.5(EP) U67.3(AGND) U67.9(PGND1) U67.11(PGND2) U104.5(GND) U104.9(EP) U113.2(GND) ; also on sheet 1 3 12 13 16 17 18 19 20 21 22 23 24 25 26 27 28 29 30 31 32 33 34 35 36 37 38 39 40 41 42 43 44 45
VCC_1V8: C52.1 C53.2 C100.1 C117.1 L7.2 R70.2 R116.1 TP41.1(TP) U14.20(PVIN_LDO2) U14.32(FB_B2) U24.4(IN) ; also on sheet 20 21 23 27 36 39 41 42 44
VCC_1V8_N: R70.4 ; also on sheet 16
VCC_1V8_P: R70.1 ; also on sheet 16
VCC_3V3_FB: C402.2 R455.2 R467.1 U67.4(FB)
VCC_3V3_MAIN: C50.1 C87.1 C104.1 C108.1 C110.1 C154.1 C320.1 C395.1 C419.1 C426.1 C502.1 C506.2 C508.1 C546.1 L12.2 R453.1 R455.1 R461.2 R618.1 R675.2 R679.1 R682.2 R778.1 TP51.1(TP) U14.4(PVIN_B1_1) U14.5(PVIN_B1_2) U14.6(PVIN_LDO1) U14.13(VSYS) U14.22(PVIN_LDO34) U14.26(PVIN_B3) U14.30(PVIN_B2) U67.1(BIAS) U104.1(VIN1) U104.2(VIN2) U104.4(VBIAS) U113.1(IN) ; also on sheet 1 28
VCC_3V3_PG: R453.2 U67.5(PGOOD)
VCC_3V3_SYS: C23.2 C92.1 C507.2 R48.2 R620.2 R621.2 R624.2 TP112.1(TP) U21.1(IN) U104.7(VOUT1) U104.8(VOUT2) ; also on sheet 3 12 16 20 21 22 24 25 26 27 28 29 31 32 33 34 35 36 37 38 39 40 41 42 43 44 45
VCC_3V3_SYS_N: R48.4 ; also on sheet 16
VCC_3V3_SYS_P: R48.1 ; also on sheet 16
VCC_5V0_EN: R676.1 R682.1 TP115.1(TP) ; also on sheet 13
VCC_CORE: C118.2 C122.1 C495.1 L5.2 R148.2 TP45.1(TP) U14.1(FB_B1)
VCC_CORE_N: R148.4 ; also on sheet 16
VCC_CORE_P: R148.1 ; also on sheet 16
VDD_1V0: C95.1 TP33.1(TP) U24.1(OUT) ; also on sheet 25 26
VDD_1V2: C112.1 C114.2 L8.2 R134.3 TP40.1(TP) U14.24(FB_B3) ; also on sheet 43
VDD_1V2_N: R134.1 ; also on sheet 16
VDD_1V2_P: R134.4 ; also on sheet 16
VDD_2V5: C357.1 TP42.1(TP) U14.23(VLDO4) ; also on sheet 19 25 26
VDD_CANUART: C51.1 C54.1 R779.2 TP122.1(TP) ; also on sheet 17
VDD_CORE: R148.3 ; also on sheet 1 16 17 18
VDD_DDR4: R134.2 ; also on sheet 17 18 19
VDD_LDO2: C106.2 C107.1 R123.3 U14.19(VLDO2)
VDD_LDO2_N: R123.1 ; also on sheet 16
VDD_LDO2_P: R123.4 ; also on sheet 16
VDDA1V8: C97.2 C98.1 R106.2 U14.21(VLDO3)
VDDA1V8_N: R106.4 ; also on sheet 16
VDDA1V8_P: R106.1 ; also on sheet 16
VDDA_1V8: R106.3 TP36.1(TP) ; also on sheet 1 17 18
VDDR_CORE: R123.2 TP39.1(TP) ; also on sheet 16 17 18
CBOOT: C413.1 U67.13(RBOOT) U67.14(CBOOT)
EXTINTn_RC: R678.1 ; also on sheet 44
LM61460_EN: R680.1 U67.7(EN/SYNC)
LM61460_RT: R454.1 U67.6(RT)
LM61460_SW: C413.2 L12.1 U67.10(SW)
LM61460_VCC: C407.1 U67.2(VCC)
PMIC_INTn: R678.2 U14.11(nINT)
PMIC_PBn: R618.2 R651.1 SW5.1 TP116.1(TP) U14.25(EN/PB/VSENSE)
PMIC_PGOOD: R620.1 TP113.1(TP) U14.18(nRSTOUT) ; also on sheet 37 44
PMIC_SCL: R638.2 TP108.1(TP) U14.10(SCL)
PMIC_SDA: R639.2 TP109.1(TP) U14.9(SDA)
PMIC_STBY: R621.1 TP104.1(TP) U14.31(MODE/STBY)
PMIC_VDDSHV_SDIO: R101.2 TP29.1(TP) ; also on sheet 22
PMIC_VDDSHV_SDIO_R: C503.1 R101.1 U14.7(VLDO1)
RESETSTATz: R615.1 ; also on sheet 21 22 23 25 26 29 34 35 39 41 42 43 44
SOC_DVDD1V8: R70.3 ; also on sheet 17 18
SoC_DVDD3V3: R48.3 ; also on sheet 17 18
SoC_I2C0_SCL: R638.1 ; also on sheet 12 24 34 35 39 44
SoC_I2C0_SDA: R639.1 ; also on sheet 12 24 34 35 39 44
SW_1V2_DDR: L8.1 U14.27(LX_B3)
SW_VCC_1V8: L7.1 U14.29(LX_B2)
SW_VCC_CORE: L5.1 U14.2(LX_B1_1) U14.3(LX_B1_2)
TEST_POWERDOWN: R651.2 ; also on sheet 3 28
TPS22965_EN: R675.1 R677.1 TP111.1(TP) U104.3(ON)
VMAIN: C396.1 C400.1 C414.1 C418.1 R680.2 U67.8(VIN1) U67.12(VIN2) ; also on sheet 12 13
VPP_1V8: R725.2 TP31.1(TP) ; also on sheet 17 18
VPP_LDO_EN: R105.1 ; also on sheet 41
VSEL_SD_SOC: R624.1 TP105.1(TP) U14.12(VSEL_SD/VSEL_DDR) ; also on sheet 34
N20239386: C494.1 U14.14(VDD1P8)
N20239533: R676.2 U14.8(GPO1)
N20240161: TP114.1(TP) U14.16(GPIO)
N20240180: R615.2 U14.28(MODE/RESET)
N20240340: R677.2 U14.17(GPO2)
N20240412: C499.2 D15.2 R679.2 SW5.3
N20242705: C86.2 C543.2 R725.1 U21.5(OUT)
N20242777: R104.1 R105.2 U21.3(EN)
N20243098: C402.1 R461.1
N20243217: R116.2 U24.3(EN)
N22047370: C526.1 U104.6(CT)
N23101345: C57.1 R779.1 R780.1 U113.5(OUT)
N23101367: R778.2 U113.3(EN)
N23101371: R780.2 R781.1 U113.4(FB)

Not connected (* = marked no-connect by the designer): U21 4(NC)*

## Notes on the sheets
sheet 14
- PERIPHERAL POWER SUPPLIES - 2
- 3.3V, 6.0 AMPS SUPPLY
- VinMin = 4.5V
  VinMax = 24V
  Vout = 3.3V @ 6A
- D-Note:
  Add a jumper or 0R for isolation or
  current measurement
  Provision can be provided for
  pre-production board and can
  be deleted for production boards
  as required
- CAD Note: Tie the feedback after the bulk caps.
- V.
- PERIPHERAL SUPPLY - ETHERNET PHY
- 1.0V, 0.5 AMPS
- 1.8V VPP, 0.5 AMPS SUPPLY
- D-Note:
  It is important to select an LDO
  with a fast transient response and
  connect the LDO output to the VPP
  pin with a low loop inductance path
  to ensure that the LDO is able to
  source the high transient load
  current, where the VPP pin never
  drops below the minimum operating
  voltage.
- D-Note:
  An alternate approach to source
  the VPP supply is to use an external
  supply. The required caps and
  discharge resistor is recommended
  to be placed near to the SoC VPP pin.
  The recommendation is to use SoC GPIO
  to control and time the external power
  supply output.
- D-Note:
  Consider using DBVR package
  (similar to VPP_1V8 LDO)
  LDO package change is due
  to the manufacturing challenges
  with QFN package
- C
- D-Note:
  Alternate part suggestion:
  TPS7A21-Q1, Automotive, 500mA, low-noise ultra-low-IQ
  high-PSRR low-dropout (LDO) voltage regulator
- D-Note:
  Given the transient current requirement during eFuse programming, using a load switch or a FET based switch may not be a
  recommended approach. It is recommended to use an LDO. A load switch or FET switch is likely to have too much voltage
  drop that can't be compensated like when using an LDO.
- CORE SUPPLY FOR CANUART VDD_CANUART
- D-Note:
  Add TPs for current
  measurement
  Follow Kelvin Current
  Sense Connection
- D-Note:
  VDD_CANUART is configured for 0.85V
  Modify R781 to 274Kto configure VDD_CANUART to 0.75V
  Example part number:: ERJ-2RKF2743X
- C
sheet 15
- SOC POWER ARCHITECTURE - PMIC
              TPS6521904 PMIC
- D-Note:
  0R resistor or jumper is added at the
  PMIC buck output for isolation or testing.
- D-Note:
  Verify the PMIC data sheet or SK schematic for the
  recommended capacitors for the buck and LDO outputs
- Input Caps for pin 4, 5, 26, 30
- D-Note:
  Show the bulk caps connection  for
  each of the DC/DC inputs separately.
  Add a 0.1 uF across the bulk caps.
  PVIN_B1_1, PVIN_B1_2 can share the
  same bulk caps.
- SILK SCREEN :
  TP45 - VCC_CORE (configured to 0.85V)
  TP41 - VCC_1V8
  TP40 - VDD_1V2
  TP29 - PMIC_VDDSHV_SDIO
  TP42 - VDD_2V5
- PMIC REGULATORS
- VOLTAGE RAIL
- CURRENT(mA)
- R-Note:
  Refer PMIC data sheet and
  PMIC schematics review
  checklist for reviewing the
  implementation of PMIC
  section on the custom board
- BUCK 1
- VCC_CORE(0.85V)
- 2700
- BUCK 2
- VCC_1V8
- 995
- BUCK 3
- VDD_1V2
- 936
- LDO 1
- VDDSHV_SDIO
- 50
- Devices Powered :
  HDMI interface
  DDR
- LDO 2
- VDD_LDO2
- 150
- LDO 3
- VDDA1V8
- 200
- LDO 4
- VDD_2V5
- 300
- C
- Configured as PB(Active Low)
- D-Note:
  RESETSTATz performs warm
  reset and has no effect on
  the PMIC. PMIC supports
  internal pull.
- Devices Powered :
  Ethernet PHY
  DDR
- I2C ADDRESS: 0x30
- CAD Note:
  Tie the PMIC buck output feedback after output bulk caps.
- R-Note:
  SD card interface IO supply voltage PMIC_VDDSHV_SDIO switching (3.3V/1.8V)
  is required to support higher speed data rates. Refer to the SoC data sheet for
  supported rates and IO voltage levels.
- SOC 3.3V IO SUPPLY
- VCC_3V3_SYS LOAD SWITCH
- PMIC ON/OFF PUSH BUTTON LOGIC
- D-Note:
  TPS22965_EN
  The GPO2 is driven by the
  PMIC to hold the load switch
  low during power-up sequence
- C
- C
- D-Note:
  Capacitor on the CT pin is provided
  for SoC IO supply slew rate control.
  SoC IO supply have slew rate
  requirements specified.
  Refer processor-specific data sheet
